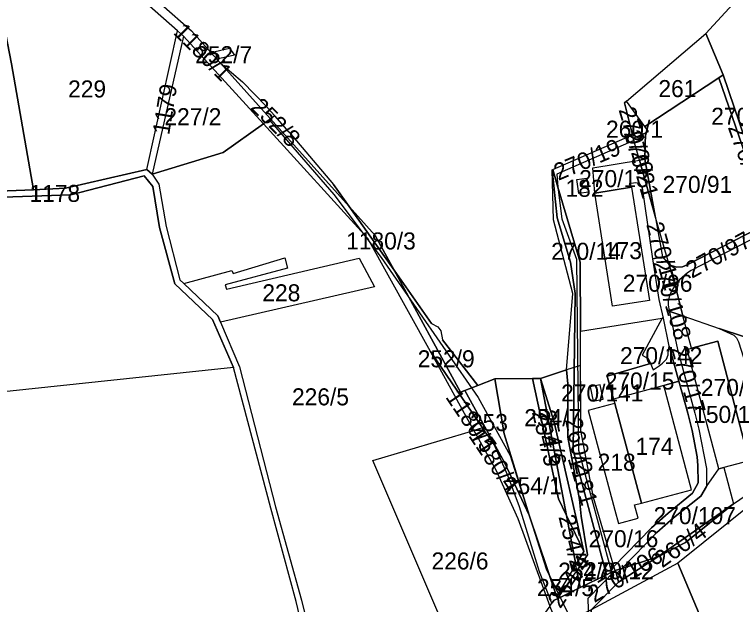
# Model space of a CAD drawing. Extents: x -623250 to -619626, y -1079612 to -1075424.
# Drawn here: x -622012.8 to -621589.3, y -1077130.2 to -1076783.7 of the extents above; entities that cross this region are included whole.
import ezdxf

# ---------------------------------------------------------------- set-up
doc = ezdxf.new("R2010")
doc.units = 0
for name, color, linetype in [('Cestní síť', 7, 'Continuous'), ('Hranice převzatá (k_ú_Džbánov - vnitřní obvod)', 7, 'Continuous'), ('Hranice šetřená (k_ú_Džbánov - vnitřní obvod)', 7, 'Continuous'), ('Parcela nároku', 7, 'Continuous'), ('Parcelní číslo', 7, 'Continuous')]:
    doc.layers.add(name, color=color, linetype=linetype)

msp = doc.modelspace()

# ---------------------------------------------------------------- linework, layer by layer
at = {"layer": 'Cestní síť'}
for p, q in [((-621863.16, -1076845.67), (-621825.24, -1076889.41)), ((-621825.24, -1076889.41), (-621797.45, -1076926.44)), ((-621797.45, -1076926.44), (-621740.43, -1077008.64)), ((-621740.43, -1077008.64), (-621721.66, -1077042.66)), ((-621721.66, -1077042.66), (-621700.59, -1077109.27)), ((-621700.59, -1077109.27), (-621674.74, -1077161.53)), ((-621675.8, -1077126.45), (-621659.97, -1077110.21)), ((-621674.74, -1077161.53), (-621675.8, -1077126.45))]:
    msp.add_line(p, q, dxfattribs=at)
at = {"layer": 'Hranice převzatá (k_ú_Džbánov - vnitřní obvod)'}
msp.add_line((-621851.36, -1076852.79), (-621825.39, -1076883.53), dxfattribs=at)
msp.add_lwpolyline([(-621767.81, -1076965.18), (-621764.04, -1076967.21), (-621762.41, -1076969.53), (-621761.31, -1076974.88)], dxfattribs=at)
at = {"layer": 'Hranice šetřená (k_ú_Džbánov - vnitřní obvod)'}
for p, q in [((-621859.85, -1076843.32), (-621866.47, -1076848.02)), ((-621851.36, -1076852.79), (-621859.85, -1076843.32)), ((-621866.47, -1076848.02), (-621890.13, -1076864.84))]:
    msp.add_line(p, q, dxfattribs=at)
for points in [[(-621890.13, -1076864.84), (-621931.83, -1076877.54), (-621934.92, -1076874.78), (-621982.79, -1076885.69), (-622001.63, -1076886.67), (-622032.21, -1076887.9), (-622055.79, -1076881.72), (-622069.07, -1076881.75), (-622087.21, -1076881.79), (-622107.66, -1076874.39), (-622119.22, -1076882.25), (-622151.27, -1076893.78), (-622162.12, -1076902.89), (-622165.94, -1076917.36)], [(-621767.81, -1076965.18), (-621789.86, -1076933.91), (-621800.97, -1076913.53), (-621816.19, -1076896.58), (-621825.39, -1076883.53)], [(-621659.97, -1077110.21), (-621660.73, -1077107.96), (-621672.77, -1077067.43), (-621680.17, -1077027.99), (-621680.35, -1076989.85), (-621688.56, -1076992.5), (-621703.92, -1076997.46), (-621708.46, -1076997.51), (-621730.61, -1076997.73), (-621740.65, -1077001.63), (-621761.31, -1076974.88)], [(-621658.06, -1077117.09), (-621659.28, -1077112.27), (-621659.97, -1077110.21)], [(-621777.05, -1077335.46), (-621776.53, -1077325.85), (-621767.08, -1077316.28), (-621754.15, -1077308.49), (-621724.62, -1077305.04), (-621725.01, -1077300.64), (-621718.03, -1077299.58), (-621700.04, -1077299.94), (-621707.97, -1077263.85), (-621661.46, -1077254.24), (-621666.99, -1077215.55), (-621668.35, -1077208.09), (-621661.04, -1077207.94), (-621670.74, -1077164.6), (-621673.7, -1077140.26), (-621674.17, -1077133.23), (-621658.06, -1077117.09)]]:
    msp.add_lwpolyline(points, dxfattribs=at)
at = {"layer": 'Parcela nároku'}
for points in [[(-622041.52, -1076673.76), (-622086.01, -1076605.12), (-622116.55, -1076539.76), (-622190.92, -1076392.28), (-622184, -1076430.23), (-622191.97, -1076479.92), (-622208.97, -1076560.35), (-622219.51, -1076644.41), (-622169.67, -1076683.52), (-622124.25, -1076725.96), (-622086.73, -1076788.54), (-622032.21, -1076887.9), (-622001.63, -1076886.67), (-622014.47, -1076812.81)], [(-621985.88, -1076732.57), (-622041.52, -1076673.76), (-622014.47, -1076812.81), (-622001.63, -1076886.67), (-621982.79, -1076885.69), (-621934.92, -1076874.78), (-621916.95, -1076793.4)], [(-621606.83, -1076795.02), (-621584.1, -1076770.14), (-621582.18, -1076779.25), (-621558.84, -1076888.77), (-621561.82, -1076902.09), (-621567.32, -1076904.86), (-621596.66, -1076819.26)], [(-621934.92, -1076874.78), (-621916.95, -1076793.4), (-621913.4, -1076796.53), (-621931.83, -1076877.54)], [(-621913.4, -1076796.53), (-621931.83, -1076877.54), (-621890.13, -1076864.84), (-621866.47, -1076848.02)], [(-621653.37, -1076834.75), (-621606.83, -1076795.02), (-621596.66, -1076819.26), (-621599.1, -1076820.91), (-621642.51, -1076849.57)], [(-621897.39, -1076806.09), (-621886.41, -1076803.58), (-621883.54, -1076807.65), (-621893.88, -1076810.01)], [(-621891.73, -1076812.41), (-621878.9, -1076823.29), (-621864.79, -1076837.81), (-621851.36, -1076852.79), (-621825.39, -1076883.53), (-621816.19, -1076896.58)], [(-621642.51, -1076849.57), (-621599.1, -1076820.91), (-621569.66, -1076906.06), (-621617.71, -1076930.85), (-621620.46, -1076931.89), (-621623.96, -1076932.1), (-621628.28, -1076930.73), (-621636.53, -1076902.24), (-621642.52, -1076868.77), (-621642.24, -1076853.29), (-621640.35, -1076852.51)], [(-621599.1, -1076820.91), (-621596.66, -1076819.26), (-621567.32, -1076904.86), (-621569.66, -1076906.06)], [(-621642.51, -1076849.57), (-621653.37, -1076834.75), (-621654.5, -1076835.71), (-621649.88, -1076854.44), (-621649.36, -1076856.31), (-621642.24, -1076853.29), (-621640.35, -1076852.51)], [(-621696.5, -1076874.78), (-621649.88, -1076854.44), (-621649.36, -1076856.31), (-621648.95, -1076857.78), (-621694.3, -1076877.51), (-621693.57, -1076885.08)], [(-621649.36, -1076856.31), (-621642.24, -1076853.29), (-621642.52, -1076868.77), (-621645.75, -1076869.3), (-621648.95, -1076857.78)], [(-621661.52, -1076955.1), (-621671.92, -1076888.65), (-621673.02, -1076873.81), (-621645.75, -1076869.3), (-621648.95, -1076857.78), (-621694.3, -1076877.51), (-621693.57, -1076885.08), (-621680.62, -1076929.1), (-621680.44, -1076969.77), (-621632.46, -1076962.15), (-621631.53, -1076962), (-621634.11, -1076951.17), (-621637.92, -1076927.2), (-621643.97, -1076885.62), (-621645.63, -1076883.05), (-621647.99, -1076882.71), (-621651.72, -1076883.2), (-621650.33, -1076885.15), (-621639.91, -1076951.61)], [(-621645.75, -1076869.3), (-621636.53, -1076902.24), (-621632.26, -1076926.14), (-621637.92, -1076927.2), (-621643.97, -1076885.62), (-621645.63, -1076883.05), (-621647.99, -1076882.71), (-621651.72, -1076883.2), (-621650.33, -1076885.15), (-621671.92, -1076888.65), (-621673.02, -1076873.81)], [(-621645.75, -1076869.3), (-621642.52, -1076868.77), (-621636.53, -1076902.24)], [(-621693.57, -1076885.08), (-621691.32, -1076903.8), (-621682.64, -1076927.43), (-621681.47, -1077039.48), (-621662.05, -1077111.23), (-621665.11, -1077112.7), (-621684.74, -1077039.66), (-621683.57, -1076947.52), (-621686.27, -1076929.22), (-621694.11, -1076903.25), (-621697.05, -1076875.01), (-621696.5, -1076874.78)], [(-621687.86, -1077031.87), (-621687.75, -1077000.59), (-621688.56, -1076992.5), (-621684.89, -1076947.58), (-621696.27, -1076904.26), (-621697.05, -1076875.01), (-621694.11, -1076903.25), (-621686.27, -1076929.22), (-621683.57, -1076947.52), (-621684.74, -1077039.66), (-621665.11, -1077112.7), (-621680.53, -1077120.3), (-621682.4, -1077110.5), (-621676.14, -1077100.94), (-621679.94, -1077078.35), (-621680.92, -1077068.47)], [(-621896.48, -1076962.86), (-621884.15, -1076991.03), (-621993.08, -1077002.63), (-622102.16, -1077014.18), (-622104.99, -1077014.33), (-622153.91, -1077016.95), (-622155.55, -1076999.57), (-622160.98, -1076969.81), (-622162.16, -1076963.36), (-622165.94, -1076917.36), (-622162.12, -1076902.89), (-622150.16, -1076897.13), (-622119.03, -1076886.71), (-622107.07, -1076878.51), (-622089.12, -1076884.94), (-622056.55, -1076885.17), (-622030.96, -1076891.48), (-621979.68, -1076889.6), (-621936.48, -1076878.52), (-621931.49, -1076884.84), (-621927.61, -1076908.77), (-621918.64, -1076941.91)], [(-621682.57, -1076880.75), (-621676.65, -1076879.84), (-621675.66, -1076888.06), (-621681.4, -1076888.81)], [(-621681.4, -1076888.81), (-621682.57, -1076880.75), (-621676.65, -1076879.84), (-621675.66, -1076888.06)], [(-621680.17, -1077027.99), (-621680.44, -1076969.77), (-621680.62, -1076929.1), (-621693.57, -1076885.08), (-621691.32, -1076903.8), (-621682.64, -1076927.43), (-621681.47, -1077039.48), (-621662.05, -1077111.23), (-621659.97, -1077110.21), (-621660.73, -1077107.96), (-621672.77, -1077067.43)], [(-621671.92, -1076888.65), (-621650.33, -1076885.15), (-621639.91, -1076951.61), (-621661.52, -1076955.1)], [(-621800.97, -1076913.53), (-621789.86, -1076933.91), (-621816.19, -1076896.58)], [(-621628.28, -1076930.73), (-621636.53, -1076902.24), (-621632.26, -1076926.14)], [(-621628.28, -1076930.73), (-621623.96, -1076932.1), (-621620.46, -1076931.89), (-621617.71, -1076930.85), (-621569.66, -1076906.06), (-621568.12, -1076909.82), (-621615.27, -1076934.15), (-621617.53, -1076935.48), (-621622.22, -1076939.58), (-621624.82, -1076942.64)], [(-621615.27, -1076934.15), (-621617.53, -1076935.48), (-621622.22, -1076939.58), (-621624.82, -1076942.64), (-621620.2, -1076960.77), (-621598.92, -1076968.16), (-621584.09, -1076972.99), (-621563.58, -1077040.98), (-621566.61, -1077041.67), (-621581.27, -1077045.75), (-621596.25, -1077049.81), (-621590.54, -1077071.06), (-621559.55, -1077050.01), (-621556.43, -1077048.44), (-621523.67, -1077019.62), (-621536.39, -1076987.8), (-621541.98, -1076973.85), (-621568.12, -1076909.82)], [(-621810.34, -1076926.81), (-621801.38, -1076943.64), (-621891.8, -1076964.45), (-621893.38, -1076960.64), (-621913.25, -1076941.81), (-621885.01, -1076934.1), (-621884.32, -1076935.78), (-621853.92, -1076926.62), (-621852.45, -1076932.73), (-621888.95, -1076942.57), (-621888.26, -1076945.03)], [(-621628.88, -1076954.37), (-621628.32, -1076957.56), (-621623.46, -1076980.43), (-621623.08, -1076981.79), (-621613.28, -1077017.83), (-621610.87, -1077027.22), (-621606.33, -1077050.25), (-621606.35, -1077060.89), (-621609.62, -1077066.59), (-621625.76, -1077079.28), (-621635.58, -1077087.96), (-621656.06, -1077108.97), (-621659.97, -1077110.21), (-621660.73, -1077107.96), (-621638.73, -1077085.17), (-621628.85, -1077076.52), (-621614.67, -1077064.79), (-621611.28, -1077058.84), (-621611.35, -1077048.48), (-621611.92, -1077043.43), (-621614.83, -1077027.99), (-621617.4, -1077017.91), (-621622.52, -1076999.13), (-621628.23, -1076978.56), (-621631.53, -1076962), (-621634.11, -1076951.17), (-621637.92, -1076927.2), (-621632.26, -1076926.14), (-621628.28, -1076930.73), (-621624.82, -1076942.64), (-621626.71, -1076945.74), (-621628.14, -1076948.85), (-621628.9, -1076952.21)], [(-621789.86, -1076933.91), (-621767.81, -1076965.18), (-621764.04, -1076967.21), (-621762.41, -1076969.53), (-621761.31, -1076974.88), (-621740.65, -1077001.63), (-621748.31, -1077004.61), (-621750.82, -1077005.51)], [(-621620.2, -1076960.77), (-621624.82, -1076942.64), (-621626.71, -1076945.74), (-621628.14, -1076948.85), (-621628.9, -1076952.21), (-621628.88, -1076954.37), (-621628.32, -1076957.56), (-621627.3, -1076958.31)], [(-621599.04, -1077050.56), (-621617.68, -1076980.42), (-621615.1, -1076979.74), (-621620.2, -1076960.77), (-621627.3, -1076958.31), (-621628.32, -1076957.56), (-621623.46, -1076980.43), (-621623.08, -1076981.79), (-621613.28, -1077017.83), (-621610.87, -1077027.22), (-621606.33, -1077050.25), (-621606.35, -1077060.89)], [(-621648.56, -1077071.64), (-621644.6, -1077070.78), (-621615.11, -1077062.9), (-621631.45, -1077001.66), (-621622.52, -1076999.13), (-621617.4, -1077017.91), (-621614.83, -1077027.99), (-621611.92, -1077043.43), (-621611.35, -1077048.48), (-621611.28, -1077058.84), (-621614.67, -1077064.79), (-621628.85, -1077076.52), (-621638.73, -1077085.17), (-621660.73, -1077107.96), (-621672.77, -1077067.43), (-621680.17, -1077027.99), (-621680.44, -1076969.77), (-621632.46, -1076962.15), (-621644.21, -1076983.78), (-621640.68, -1076985.78), (-621639.3, -1076988.73), (-621664.75, -1076996.15), (-621660.96, -1077009.58), (-621660.26, -1077012.19), (-621664.16, -1077013.24), (-621675.81, -1077016.38), (-621660.16, -1077074.77), (-621658.07, -1077082.55), (-621646.41, -1077079.48)], [(-621628.23, -1076978.56), (-621631.53, -1076962), (-621632.46, -1076962.15), (-621644.21, -1076983.78), (-621640.68, -1076985.78), (-621639.3, -1076988.73), (-621637.61, -1076992.32), (-621634.07, -1076990.08), (-621632.17, -1076988.5), (-621629.93, -1076986.17), (-621628.94, -1076983.6), (-621628.81, -1076982.45)], [(-621598.92, -1076968.16), (-621590.34, -1076972.12), (-621588.81, -1076973.64), (-621587.52, -1076975.91), (-621566.61, -1077041.67), (-621581.27, -1077045.75), (-621599.79, -1076975.67), (-621615.1, -1076979.74), (-621620.2, -1076960.77)], [(-621584.09, -1076972.99), (-621598.92, -1076968.16), (-621590.34, -1076972.12), (-621588.81, -1076973.64), (-621587.52, -1076975.91), (-621566.61, -1077041.67), (-621563.58, -1077040.98)], [(-621639.3, -1076988.73), (-621637.61, -1076992.32), (-621634.07, -1076990.08), (-621632.17, -1076988.5), (-621629.93, -1076986.17), (-621628.94, -1076983.6), (-621628.81, -1076982.45), (-621628.23, -1076978.56), (-621622.52, -1076999.13), (-621631.45, -1077001.66), (-621660.96, -1077009.58), (-621664.75, -1076996.15)], [(-621617.68, -1076980.42), (-621615.1, -1076979.74), (-621599.79, -1076975.67), (-621581.27, -1077045.75), (-621596.25, -1077049.81), (-621599.04, -1077050.56)], [(-621768.44, -1076981.74), (-621737.82, -1077026.43), (-621742.89, -1077027.94)], [(-621862.28, -1077073.68), (-621884.15, -1076991.03), (-621993.08, -1077002.63), (-622102.16, -1077014.18), (-622094.75, -1077078.52), (-622077.89, -1077147.06), (-622076.74, -1077150.89), (-622049.49, -1077211.69), (-622030.93, -1077247.2), (-622020.83, -1077286.22), (-621987.11, -1077301.08), (-621948.12, -1077317.22), (-621892.3, -1077330.5), (-621883.37, -1077321.39), (-621873.67, -1077293.17), (-621859.64, -1077268.41), (-621832.26, -1077224.99), (-621829.56, -1077216.51), (-621831.64, -1077194.31), (-621847.29, -1077128.33)], [(-621703.92, -1076997.46), (-621688.56, -1076992.5), (-621687.75, -1077000.59), (-621687.86, -1077031.87), (-621680.92, -1077068.47), (-621679.94, -1077078.35), (-621676.14, -1077100.94), (-621682.4, -1077110.5), (-621683.12, -1077106.71), (-621678.46, -1077099.03), (-621695.88, -1077023.22)], [(-621725.22, -1077029.96), (-621710.49, -1077077.66), (-621725, -1077046.79), (-621748.31, -1077004.61), (-621740.65, -1077001.63), (-621730.61, -1076997.73)], [(-621708.46, -1076997.51), (-621693.26, -1077068.16), (-621688.61, -1077077.85), (-621683.12, -1077106.71), (-621694.37, -1077125.25), (-621710.49, -1077077.66), (-621725.22, -1077029.96), (-621730.61, -1076997.73)], [(-621708.46, -1076997.51), (-621703.92, -1076997.46), (-621688.61, -1077077.85), (-621693.26, -1077068.16)], [(-621703.92, -1076997.46), (-621695.88, -1077023.22), (-621678.46, -1077099.03), (-621688.61, -1077077.85)], [(-621674.59, -1077002.45), (-621673, -1077010.73), (-621666.99, -1077009.68), (-621668.75, -1077001.22)], [(-621668.75, -1077001.22), (-621674.59, -1077002.45), (-621673, -1077010.73), (-621666.99, -1077009.68)], [(-621631.45, -1077001.66), (-621660.96, -1077009.58), (-621660.26, -1077012.19), (-621644.6, -1077070.78), (-621615.11, -1077062.9)], [(-621646.41, -1077079.48), (-621648.56, -1077071.64), (-621644.6, -1077070.78), (-621660.26, -1077012.19), (-621664.16, -1077013.24), (-621675.81, -1077016.38), (-621660.16, -1077074.77), (-621658.07, -1077082.55)], [(-621742.89, -1077027.94), (-621730.03, -1077051.19), (-621717.08, -1077079.76), (-621698.44, -1077131.08), (-621712.03, -1077149.92), (-621740.17, -1077171.93), (-621746.44, -1077175.87), (-621802.34, -1077045.59)], [(-621737.82, -1077026.43), (-621742.89, -1077027.94), (-621730.03, -1077051.19), (-621717.08, -1077079.76), (-621698.44, -1077131.08), (-621697.15, -1077129.38), (-621704.43, -1077111.1), (-621716.26, -1077072.94), (-621722.92, -1077054.35), (-621730.97, -1077036.31)], [(-621609.62, -1077066.59), (-621606.35, -1077060.89), (-621599.04, -1077050.56), (-621596.25, -1077049.81), (-621590.54, -1077071.06), (-621634.95, -1077102.27), (-621656.06, -1077108.97), (-621635.58, -1077087.96), (-621625.76, -1077079.28)], [(-621523.17, -1077195.12), (-621571.7, -1077066.1), (-621579.59, -1077070.93), (-621623.27, -1077105.92), (-621571.51, -1077228.57), (-621549.32, -1077220.52), (-621537.72, -1077208.73)], [(-621634.95, -1077102.27), (-621590.54, -1077071.06), (-621618.73, -1077093.83)], [(-621688.61, -1077077.85), (-621678.46, -1077099.03), (-621683.12, -1077106.71)], [(-621659.28, -1077112.27), (-621656.06, -1077108.97), (-621634.95, -1077102.27), (-621658.06, -1077117.09)], [(-621682.4, -1077110.5), (-621683.12, -1077106.71), (-621694.37, -1077125.25), (-621693.84, -1077126.83)], [(-621570.38, -1077230.98), (-621571.51, -1077228.57), (-621623.27, -1077105.92), (-621674.17, -1077133.23), (-621673.7, -1077140.26), (-621670.74, -1077164.6), (-621661.04, -1077207.94), (-621624.64, -1077201.52), (-621606.64, -1077245.37), (-621587.33, -1077241.87)], [(-621693.84, -1077126.83), (-621682.4, -1077110.5), (-621680.53, -1077120.3)], [(-621659.97, -1077110.21), (-621656.06, -1077108.97), (-621659.28, -1077112.27)]]:
    msp.add_lwpolyline(points, close=True, dxfattribs=at)
for points in [[(-621926.64, -1076777.67), (-621908.85, -1076793.33), (-621897.39, -1076806.09), (-621893.88, -1076810.01), (-621891.73, -1076812.41), (-621816.19, -1076896.58), (-621789.86, -1076933.91), (-621750.82, -1077005.51), (-621748.31, -1077004.61), (-621725, -1077046.79), (-621710.49, -1077077.66), (-621694.37, -1077125.25), (-621693.84, -1077126.83), (-621695.81, -1077127.62), (-621697.15, -1077129.38), (-621704.43, -1077111.1), (-621716.26, -1077072.94), (-621722.92, -1077054.35), (-621730.97, -1077036.31), (-621737.82, -1077026.43), (-621768.44, -1076981.74), (-621805.21, -1076915.25), (-621866.47, -1076848.02), (-621913.4, -1076796.53), (-621916.95, -1076793.4), (-621985.88, -1076732.57)], [(-621926.64, -1076777.67), (-621908.85, -1076793.33), (-621897.39, -1076806.09), (-621886.41, -1076803.58), (-621883.54, -1076807.65), (-621893.88, -1076810.01), (-621891.73, -1076812.41), (-621878.9, -1076823.29), (-621864.79, -1076837.81), (-621851.36, -1076852.79), (-621825.39, -1076883.53), (-621816.19, -1076896.58), (-621800.97, -1076913.53), (-621789.86, -1076933.91), (-621767.81, -1076965.18), (-621764.04, -1076967.21), (-621762.41, -1076969.53), (-621761.31, -1076974.88), (-621740.65, -1077001.63), (-621730.61, -1076997.73), (-621708.46, -1076997.51), (-621703.92, -1076997.46), (-621688.56, -1076992.5), (-621684.89, -1076947.58), (-621696.27, -1076904.26), (-621697.05, -1076875.01), (-621696.5, -1076874.78), (-621649.88, -1076854.44), (-621654.5, -1076835.71), (-621653.37, -1076834.75), (-621606.83, -1076795.02), (-621584.1, -1076770.14)], [(-621746.44, -1077175.87), (-621802.34, -1077045.59), (-621742.89, -1077027.94), (-621768.44, -1076981.74), (-621805.21, -1076915.25), (-621866.47, -1076848.02), (-621890.13, -1076864.84), (-621931.83, -1076877.54), (-621928.03, -1076883.35), (-621923.74, -1076908.31), (-621915.61, -1076939.57), (-621913.25, -1076941.81), (-621885.01, -1076934.1), (-621884.32, -1076935.78), (-621853.92, -1076926.62), (-621852.45, -1076932.73), (-621888.95, -1076942.57), (-621888.26, -1076945.03), (-621810.34, -1076926.81), (-621801.38, -1076943.64), (-621891.8, -1076964.45), (-621880.56, -1076990.6), (-621859.46, -1077072.79), (-621844.23, -1077127.58), (-621827.5, -1077194.48)], [(-622032.21, -1076887.9), (-622001.63, -1076886.67), (-621982.79, -1076885.69), (-621934.92, -1076874.78), (-621931.83, -1076877.54), (-621928.03, -1076883.35), (-621923.74, -1076908.31), (-621915.61, -1076939.57), (-621913.25, -1076941.81), (-621893.38, -1076960.64), (-621891.8, -1076964.45), (-621880.56, -1076990.6), (-621859.46, -1077072.79), (-621844.23, -1077127.58), (-621827.5, -1077194.48)], [(-621831.64, -1077194.31), (-621847.29, -1077128.33), (-621862.28, -1077073.68), (-621884.15, -1076991.03), (-621896.48, -1076962.86), (-621918.64, -1076941.91), (-621927.61, -1076908.77), (-621931.49, -1076884.84), (-621936.48, -1076878.52), (-621979.68, -1076889.6), (-622030.96, -1076891.48)], [(-621579.59, -1077070.93), (-621623.27, -1077105.92), (-621674.17, -1077133.23), (-621676.84, -1077134.66), (-621692.89, -1077143.94), (-621698.44, -1077131.08), (-621697.15, -1077129.38), (-621695.81, -1077127.62), (-621693.84, -1077126.83), (-621680.53, -1077120.3), (-621665.11, -1077112.7), (-621662.05, -1077111.23), (-621659.97, -1077110.21), (-621659.28, -1077112.27), (-621658.06, -1077117.09), (-621634.95, -1077102.27), (-621618.73, -1077093.83), (-621590.54, -1077071.06), (-621559.55, -1077050.01)]]:
    msp.add_lwpolyline(points, dxfattribs=at)

# ---------------------------------------------------------------- texts
at = {"layer": 'Parcelní číslo'}
for s, rotation, p in [('1180/1', 314.9809, (-621919.94, -1076794.82)), ('1179', 80.6819, (-621921.92, -1076854.88)), ('252/8', 314.9809, (-621874.57, -1076838.79)), ('270/20', 286.2179, (-621658.07, -1076839.68)), ('270/92', 289.283, (-621593.94, -1076849.95)), ('270/21', 285.9132, (-621654.99, -1076853.26)), ('270/19', 23.0661, (-621693.36, -1076881.49)), ('270/11', 285.5809, (-621641.82, -1076907.15)), ('270/97', 28.6818, (-621614.98, -1076939.02)), ('270/108', 286.2476, (-621638.19, -1076929.34)), ('270/17', 285.4522, (-621627.19, -1076979.8)), ('1180/5', 304.0133, (-621759.98, -1077008.4)), ('254/3', 283.3571, (-621708.93, -1077017.19)), ('254/6', 281.7834, (-621704.94, -1077017.07)), ('260/2', 281.7616, (-621689.44, -1077021.71)), ('1180/4', 303.7514, (-621746.44, -1077031.1)), ('1181', 286.4361, (-621687.95, -1077044.41)), ('254/2', 283.6758, (-621693.36, -1077078.64)), ('260/4', 35.5262, (-621632.34, -1077109.06)), ('270/106', 31.5042, (-621672.18, -1077129.41)), ('254/4', 55.5481, (-621692.21, -1077133.05))]:
    msp.add_text(s, height=10, rotation=rotation, dxfattribs=at).set_placement(p)
for s, p in [('252/7', (-621906.63, -1076812.38)), ('229', (-621981.24, -1076832.48)), ('261', (-621634.61, -1076832.28)), ('227/2', (-621924.71, -1076848.78)), ('270/93', (-621603.57, -1076848.53)), ('260/1', (-621665.37, -1076856.12)), ('270/13', (-621681.14, -1076885.13)), ('270/91', (-621632.12, -1076888.54)), ('182', (-621689.16, -1076890.83)), ('1178', (-622003.94, -1076893.82)), ('1180/3', (-621817.95, -1076921.73)), ('270/14', (-621697.57, -1076927.82)), ('173', (-621666.6, -1076927.42)), ('270/96', (-621655.49, -1076946.55)), ('228', (-621867.18, -1076952.19)), ('270/142', (-621657.14, -1076989.07)), ('252/9', (-621775.95, -1076990.93)), ('270/15', (-621666.11, -1077003.97)), ('270/141', (-621691.73, -1077010.97)), ('270/95', (-621609.66, -1077007.77)), ('226/5', (-621849.76, -1077013.26)), ('150/1', (-621614.16, -1077023.59)), ('254/7', (-621713.37, -1077025.5)), ('253', (-621745.26, -1077028.33)), ('174', (-621648.07, -1077042.33)), ('218', (-621670.27, -1077051.62)), ('254/1', (-621724.73, -1077065.45)), ('270/107', (-621637.43, -1077083.03)), ('270/16', (-621675.55, -1077096.58)), ('226/6', (-621767.82, -1077109.61)), ('254/8', (-621693.42, -1077115.62)), ('270/12', (-621678.28, -1077115.38)), ('254/5', (-621705.88, -1077125.22))]:
    msp.add_text(s, height=10, dxfattribs=at).set_placement(p)

doc.saveas('drawing.dxf')
